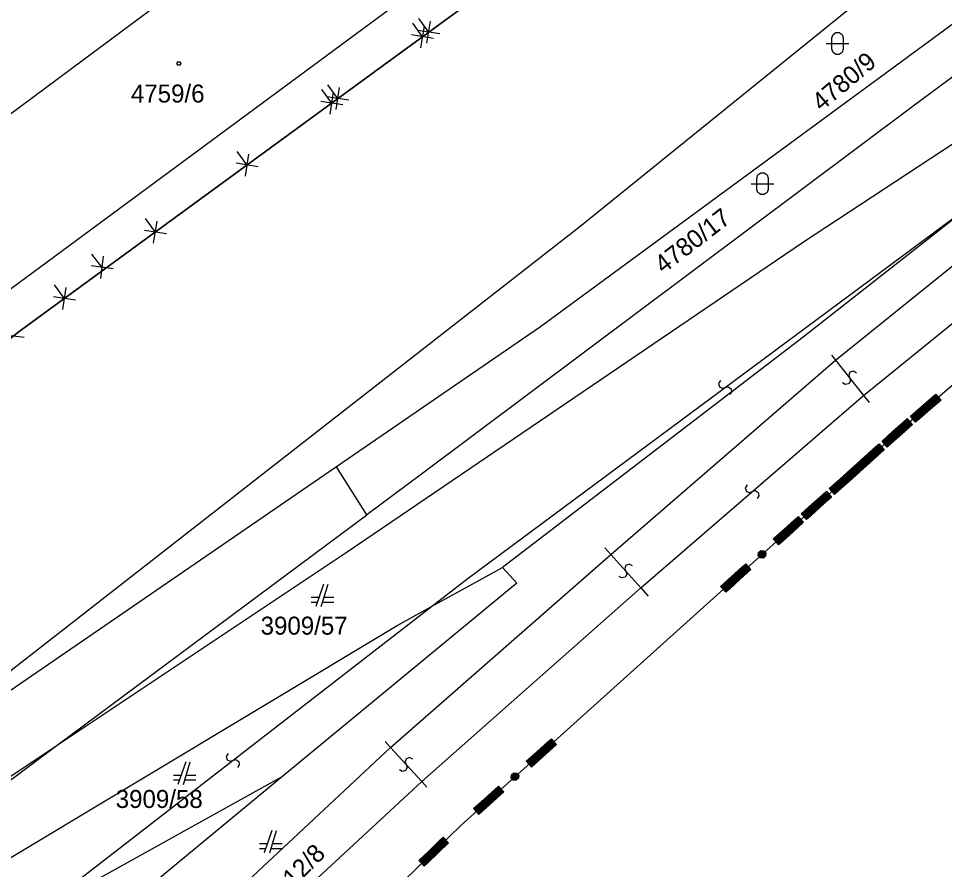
# Model space of a CAD drawing. Extents: x -266179 to -264727, y -1243225 to -1241702.
# Drawn here: x -265525.4 to -265443.1, y -1243065.9 to -1242990.2 of the extents above; entities that cross this region are included whole.
import ezdxf

# ---------------------------------------------------------------- set-up
doc = ezdxf.new("R2010")
doc.units = 0
for name, color, linetype in [('Vrstva 1', 7, 'Continuous'), ('Vrstva 19', 7, 'Continuous'), ('Vrstva 2', 7, 'Continuous'), ('Vrstva 21', 7, 'Continuous')]:
    doc.layers.add(name, color=color, linetype=linetype)

msp = doc.modelspace()

# ---------------------------------------------------------------- linework, layer by layer
at = {"layer": 'Vrstva 1'}
for p, q in [((-265475.52, -1243008.72), (-265434.39, -1242975.43)), ((-265495.14, -1242975.72), (-265534.92, -1243005.24)), ((-265418.16, -1242977.61), (-265445.92, -1242998.02)), ((-265455.74, -1243010.14), (-265412.81, -1242981.9)), ((-265527.48, -1243015.25), (-265487.69, -1242985.87)), ((-265485.47, -1242988.9), (-265493, -1242994.41)), ((-265440.4, -1242989.28), (-265479.04, -1243017.66)), ((-265493, -1242994.41), (-265525.37, -1243018.08)), ((-265445.92, -1242998.02), (-265489.73, -1243030.85)), ((-265439.81, -1243006.11), (-265455.69, -1243018.57)), ((-265534.18, -1243054.5), (-265475.52, -1243008.72)), ((-265496.21, -1243037.67), (-265455.74, -1243010.14)), ((-265431.41, -1243013.36), (-265447.33, -1243027.08)), ((-265525.37, -1243018.08), (-265529.85, -1243021.55)), ((-265479.04, -1243017.66), (-265497.17, -1243030.1)), ((-265455.69, -1243018.57), (-265482.42, -1243039.05)), ((-265447.33, -1243027.08), (-265454.5, -1243033.53)), ((-265497.17, -1243030.1), (-265541.9, -1243060.8)), ((-265494.46, -1243034.38), (-265497.17, -1243030.1)), ((-265489.73, -1243030.85), (-265494.46, -1243034.38)), ((-265454.5, -1243033.53), (-265486.12, -1243061.99)), ((-265522, -1243054.85), (-265494.46, -1243034.38)), ((-265522, -1243054.85), (-265496.21, -1243037.67)), ((-265488.71, -1243042.52), (-265482.42, -1243039.05)), ((-265482.42, -1243039.05), (-265481.14, -1243040.45)), ((-265481.14, -1243040.45), (-265501.93, -1243057.61)), ((-265498.31, -1243040.53), (-265499.01, -1243042.53)), ((-265498.51, -1243042.53), (-265497.91, -1243040.53)), ((-265498.73, -1243041.73), (-265499.41, -1243041.73)), ((-265499.41, -1243042.13), (-265498.87, -1243042.13)), ((-265498.39, -1243042.13), (-265497.41, -1243042.13)), ((-265497.41, -1243041.73), (-265498.27, -1243041.73)), ((-265491.77, -1243044.2), (-265488.71, -1243042.52)), ((-265531.47, -1243068.04), (-265491.77, -1243044.2)), ((-265534.79, -1243063.37), (-265522, -1243054.85)), ((-265533.94, -1243063.73), (-265522, -1243054.85)), ((-265510.56, -1243056.33), (-265511.26, -1243058.33)), ((-265510.76, -1243058.33), (-265510.16, -1243056.33)), ((-265524.05, -1243069.88), (-265501.93, -1243057.61)), ((-265501.93, -1243057.61), (-265523.24, -1243075.2)), ((-265510.98, -1243057.53), (-265511.66, -1243057.53)), ((-265509.66, -1243057.53), (-265510.52, -1243057.53)), ((-265511.66, -1243057.93), (-265511.12, -1243057.93)), ((-265510.64, -1243057.93), (-265509.66, -1243057.93)), ((-265502.9, -1243062.43), (-265503.6, -1243064.43)), ((-265503.1, -1243064.43), (-265502.5, -1243062.43)), ((-265486.12, -1243061.99), (-265499.6, -1243075.05)), ((-265503.32, -1243063.63), (-265504, -1243063.63)), ((-265504, -1243064.03), (-265503.46, -1243064.03)), ((-265502.98, -1243064.03), (-265502, -1243064.03)), ((-265502, -1243063.63), (-265502.86, -1243063.63))]:
    msp.add_line(p, q, dxfattribs=at)
for points in [[(-265453.13, -1242991.96), (-265453.03, -1242991.67), (-265452.78, -1242991.49), (-265452.47, -1242991.49), (-265452.22, -1242991.67), (-265452.12, -1242991.96), (-265452.12, -1242992.96), (-265452.22, -1242993.25), (-265452.47, -1242993.43), (-265452.78, -1242993.43), (-265453.03, -1242993.25), (-265453.13, -1242992.96)], [(-265511.09, -1242994.09), (-265511, -1242994.24), (-265511.09, -1242994.39), (-265511.27, -1242994.39), (-265511.36, -1242994.24), (-265511.27, -1242994.09)], [(-265459.8, -1243004.43), (-265459.7, -1243004.14), (-265459.45, -1243003.96), (-265459.14, -1243003.96), (-265458.89, -1243004.14), (-265458.79, -1243004.43), (-265458.79, -1243005.43), (-265458.89, -1243005.72), (-265459.14, -1243005.9), (-265459.45, -1243005.9), (-265459.7, -1243005.72), (-265459.8, -1243005.43)]]:
    msp.add_lwpolyline(points, close=True, dxfattribs=at)
for points in [[(-265453.63, -1242992.46), (-265452.36, -1242992.46), (-265451.63, -1242992.46)], [(-265460.3, -1243004.93), (-265459.03, -1243004.93), (-265458.3, -1243004.93)]]:
    msp.add_lwpolyline(points, dxfattribs=at)
at = {"layer": 'Vrstva 19'}
for p, q in [((-265431.41, -1243013.36), (-265447.33, -1243027.08)), ((-265447.33, -1243027.08), (-265454.5, -1243033.53)), ((-265454.5, -1243033.53), (-265486.12, -1243061.99)), ((-265486.12, -1243061.99), (-265499.6, -1243075.05))]:
    msp.add_line(p, q, dxfattribs=at)
for points in [[(-265443.427, -1243024.179), (-265444.389, -1243025.008), (-265445.351, -1243025.837), (-265445.7, -1243026.138), (-265446.157, -1243025.608), (-265445.195, -1243024.778), (-265444.233, -1243023.949), (-265443.884, -1243023.649), (-265443.427, -1243024.179), (-265443.526, -1243024.172), (-265444.488, -1243025.001), (-265445.45, -1243025.83), (-265445.708, -1243026.052), (-265445.76, -1243025.991), (-265444.798, -1243025.162), (-265443.836, -1243024.333), (-265443.578, -1243024.111), (-265443.631, -1243024.051), (-265444.593, -1243024.88), (-265445.555, -1243025.709), (-265445.812, -1243025.931), (-265445.864, -1243025.87), (-265444.902, -1243025.041), (-265443.94, -1243024.212), (-265443.683, -1243023.99), (-265443.735, -1243023.929), (-265444.697, -1243024.759), (-265445.659, -1243025.588), (-265445.917, -1243025.81), (-265445.969, -1243025.749), (-265445.007, -1243024.92), (-265444.045, -1243024.091), (-265443.787, -1243023.869), (-265443.84, -1243023.808), (-265444.802, -1243024.637), (-265445.763, -1243025.466), (-265446.021, -1243025.688), (-265446.073, -1243025.628), (-265445.111, -1243024.799), (-265444.149, -1243023.97), (-265443.892, -1243023.748)], [(-265445.976, -1243026.334), (-265446.92, -1243027.183), (-265447.865, -1243028.032), (-265448.207, -1243028.34), (-265448.675, -1243027.819), (-265447.73, -1243026.97), (-265446.786, -1243026.121), (-265446.444, -1243025.813), (-265445.976, -1243026.334), (-265446.06, -1243026.315), (-265447.004, -1243027.164), (-265447.949, -1243028.014), (-265448.201, -1243028.241), (-265448.255, -1243028.181), (-265447.311, -1243027.332), (-265446.366, -1243026.483), (-265446.113, -1243026.256), (-265446.167, -1243026.196), (-265447.111, -1243027.045), (-265448.056, -1243027.895), (-265448.308, -1243028.122), (-265448.362, -1243028.062), (-265447.418, -1243027.213), (-265446.473, -1243026.364), (-265446.22, -1243026.137), (-265446.274, -1243026.077), (-265447.218, -1243026.926), (-265448.163, -1243027.776), (-265448.415, -1243028.003), (-265448.469, -1243027.944), (-265447.525, -1243027.094), (-265446.58, -1243026.245), (-265446.327, -1243026.018), (-265446.381, -1243025.958), (-265447.325, -1243026.807), (-265448.27, -1243027.657), (-265448.522, -1243027.884), (-265448.576, -1243027.825), (-265447.632, -1243026.975), (-265446.687, -1243026.126), (-265446.434, -1243025.899)], [(-265448.471, -1243028.578), (-265449.415, -1243029.427), (-265450.359, -1243030.277), (-265450.702, -1243030.584), (-265451.17, -1243030.064), (-265450.225, -1243029.214), (-265449.281, -1243028.365), (-265448.939, -1243028.058), (-265448.471, -1243028.578), (-265448.555, -1243028.56), (-265449.499, -1243029.409), (-265450.443, -1243030.258), (-265450.696, -1243030.485), (-265450.75, -1243030.426), (-265449.805, -1243029.577), (-265448.861, -1243028.727), (-265448.608, -1243028.5), (-265448.662, -1243028.441), (-265449.606, -1243029.29), (-265450.55, -1243030.139), (-265450.803, -1243030.366), (-265450.857, -1243030.307), (-265449.912, -1243029.458), (-265448.968, -1243028.608), (-265448.715, -1243028.381), (-265448.769, -1243028.322), (-265449.713, -1243029.171), (-265450.657, -1243030.02), (-265450.91, -1243030.247), (-265450.964, -1243030.188), (-265450.019, -1243029.339), (-265449.075, -1243028.489), (-265448.822, -1243028.262), (-265448.876, -1243028.203), (-265449.82, -1243029.052), (-265450.764, -1243029.901), (-265451.017, -1243030.128), (-265451.071, -1243030.069), (-265450.126, -1243029.22), (-265449.182, -1243028.37), (-265448.929, -1243028.143)], [(-265449.357, -1243029.334), (-265449.558, -1243029.514), (-265449.826, -1243029.5), (-265450.007, -1243029.299), (-265449.992, -1243029.031), (-265449.792, -1243028.851), (-265449.523, -1243028.865), (-265449.343, -1243029.066), (-265449.357, -1243029.334), (-265449.391, -1243029.311), (-265449.57, -1243029.471), (-265449.683, -1243029.465), (-265449.385, -1243029.198), (-265449.379, -1243029.085), (-265449.796, -1243029.459), (-265449.849, -1243029.4), (-265449.433, -1243029.025), (-265449.486, -1243028.966), (-265449.903, -1243029.34), (-265449.956, -1243029.281), (-265449.54, -1243028.906), (-265449.653, -1243028.9), (-265449.95, -1243029.168), (-265449.944, -1243029.055), (-265449.766, -1243028.894)], [(-265450.66, -1243030.546), (-265451.605, -1243031.396), (-265452.549, -1243032.245), (-265452.891, -1243032.552), (-265453.359, -1243032.032), (-265452.415, -1243031.183), (-265451.471, -1243030.333), (-265451.128, -1243030.026), (-265450.66, -1243030.546), (-265450.759, -1243030.541), (-265451.704, -1243031.39), (-265452.648, -1243032.24), (-265452.901, -1243032.467), (-265452.954, -1243032.407), (-265452.01, -1243031.558), (-265451.066, -1243030.709), (-265450.813, -1243030.482), (-265450.866, -1243030.422), (-265451.811, -1243031.271), (-265452.755, -1243032.121), (-265453.008, -1243032.348), (-265453.061, -1243032.288), (-265452.117, -1243031.439), (-265451.173, -1243030.59), (-265450.92, -1243030.363), (-265450.973, -1243030.303), (-265451.918, -1243031.152), (-265452.862, -1243032.002), (-265453.115, -1243032.229), (-265453.168, -1243032.169), (-265452.224, -1243031.32), (-265451.28, -1243030.471), (-265451.027, -1243030.244), (-265451.08, -1243030.184), (-265452.025, -1243031.033), (-265452.969, -1243031.883), (-265453.222, -1243032.11), (-265453.275, -1243032.05), (-265452.331, -1243031.201), (-265451.387, -1243030.352), (-265451.134, -1243030.125)], [(-265451.852, -1243031.578), (-265452.053, -1243031.759), (-265452.321, -1243031.744), (-265452.501, -1243031.544), (-265452.487, -1243031.275), (-265452.286, -1243031.095), (-265452.018, -1243031.109), (-265451.838, -1243031.31), (-265451.852, -1243031.578), (-265451.886, -1243031.555), (-265452.064, -1243031.716), (-265452.177, -1243031.71), (-265451.88, -1243031.442), (-265451.874, -1243031.329), (-265452.29, -1243031.704), (-265452.344, -1243031.644), (-265451.927, -1243031.27), (-265451.981, -1243031.21), (-265452.397, -1243031.585), (-265452.451, -1243031.525), (-265452.034, -1243031.151), (-265452.147, -1243031.145), (-265452.445, -1243031.412), (-265452.439, -1243031.299), (-265452.26, -1243031.139)], [(-265453.155, -1243032.791), (-265454.1, -1243033.64), (-265455.044, -1243034.489), (-265455.386, -1243034.797), (-265455.854, -1243034.276), (-265454.91, -1243033.427), (-265453.965, -1243032.578), (-265453.623, -1243032.27), (-265453.155, -1243032.791), (-265453.254, -1243032.785), (-265454.198, -1243033.635), (-265455.143, -1243034.484), (-265455.396, -1243034.711), (-265455.449, -1243034.652), (-265454.505, -1243033.803), (-265453.56, -1243032.953), (-265453.308, -1243032.726), (-265453.361, -1243032.666), (-265454.305, -1243033.516), (-265455.25, -1243034.365), (-265455.503, -1243034.592), (-265455.556, -1243034.533), (-265454.612, -1243033.684), (-265453.667, -1243032.834), (-265453.415, -1243032.607), (-265453.468, -1243032.548), (-265454.412, -1243033.397), (-265455.357, -1243034.246), (-265455.61, -1243034.473), (-265455.663, -1243034.414), (-265454.719, -1243033.565), (-265453.774, -1243032.715), (-265453.522, -1243032.488), (-265453.575, -1243032.429), (-265454.519, -1243033.278), (-265455.464, -1243034.127), (-265455.717, -1243034.354), (-265455.77, -1243034.295), (-265454.826, -1243033.446), (-265453.881, -1243032.596), (-265453.629, -1243032.369)], [(-265455.64, -1243035.029), (-265456.584, -1243035.879), (-265457.528, -1243036.728), (-265457.87, -1243037.035), (-265458.338, -1243036.515), (-265457.394, -1243035.666), (-265456.45, -1243034.816), (-265456.108, -1243034.509), (-265455.64, -1243035.029), (-265455.724, -1243035.011), (-265456.668, -1243035.86), (-265457.612, -1243036.709), (-265457.865, -1243036.937), (-265457.919, -1243036.877), (-265456.974, -1243036.028), (-265456.03, -1243035.179), (-265455.777, -1243034.951), (-265455.831, -1243034.892), (-265456.775, -1243035.741), (-265457.719, -1243036.59), (-265457.972, -1243036.818), (-265458.026, -1243036.758), (-265457.081, -1243035.909), (-265456.137, -1243035.06), (-265455.884, -1243034.832), (-265455.938, -1243034.773), (-265456.882, -1243035.622), (-265457.826, -1243036.471), (-265458.079, -1243036.699), (-265458.133, -1243036.639), (-265457.188, -1243035.79), (-265456.244, -1243034.941), (-265455.991, -1243034.713), (-265456.045, -1243034.654), (-265456.989, -1243035.503), (-265457.933, -1243036.352), (-265458.186, -1243036.58), (-265458.24, -1243036.52), (-265457.295, -1243035.671), (-265456.351, -1243034.822), (-265456.098, -1243034.594)], [(-265459.021, -1243038.029), (-265459.221, -1243038.21), (-265459.49, -1243038.196), (-265459.67, -1243037.995), (-265459.656, -1243037.727), (-265459.455, -1243037.546), (-265459.187, -1243037.56), (-265459.006, -1243037.761), (-265459.021, -1243038.029), (-265459.055, -1243038.006), (-265459.233, -1243038.167), (-265459.346, -1243038.161), (-265459.049, -1243037.893), (-265459.043, -1243037.78), (-265459.459, -1243038.155), (-265459.513, -1243038.095), (-265459.096, -1243037.721), (-265459.15, -1243037.661), (-265459.566, -1243038.036), (-265459.62, -1243037.976), (-265459.203, -1243037.602), (-265459.316, -1243037.596), (-265459.614, -1243037.863), (-265459.608, -1243037.75), (-265459.429, -1243037.59)], [(-265460.324, -1243039.242), (-265461.268, -1243040.091), (-265462.213, -1243040.94), (-265462.555, -1243041.248), (-265463.023, -1243040.727), (-265462.079, -1243039.878), (-265461.134, -1243039.029), (-265460.792, -1243038.721), (-265460.324, -1243039.242), (-265460.423, -1243039.237), (-265461.367, -1243040.086), (-265462.312, -1243040.935), (-265462.564, -1243041.162), (-265462.618, -1243041.103), (-265461.674, -1243040.254), (-265460.729, -1243039.405), (-265460.476, -1243039.177), (-265460.53, -1243039.118), (-265461.474, -1243039.967), (-265462.419, -1243040.816), (-265462.671, -1243041.044), (-265462.725, -1243040.984), (-265461.781, -1243040.135), (-265460.836, -1243039.286), (-265460.583, -1243039.058), (-265460.637, -1243038.999), (-265461.581, -1243039.848), (-265462.526, -1243040.697), (-265462.778, -1243040.925), (-265462.832, -1243040.865), (-265461.888, -1243040.016), (-265460.943, -1243039.167), (-265460.69, -1243038.939), (-265460.744, -1243038.88), (-265461.688, -1243039.729), (-265462.633, -1243040.578), (-265462.885, -1243040.806), (-265462.939, -1243040.746), (-265461.995, -1243039.897), (-265461.05, -1243039.048), (-265460.797, -1243038.82)], [(-265477.597, -1243054.793), (-265478.541, -1243055.642), (-265479.486, -1243056.491), (-265479.828, -1243056.799), (-265480.296, -1243056.278), (-265479.352, -1243055.429), (-265478.407, -1243054.58), (-265478.065, -1243054.272), (-265477.597, -1243054.793), (-265477.681, -1243054.774), (-265478.625, -1243055.623), (-265479.57, -1243056.472), (-265479.823, -1243056.7), (-265479.876, -1243056.64), (-265478.932, -1243055.791), (-265477.987, -1243054.942), (-265477.735, -1243054.714), (-265477.788, -1243054.655), (-265478.732, -1243055.504), (-265479.677, -1243056.353), (-265479.93, -1243056.581), (-265479.983, -1243056.521), (-265479.039, -1243055.672), (-265478.094, -1243054.823), (-265477.842, -1243054.595), (-265477.895, -1243054.536), (-265478.839, -1243055.385), (-265479.784, -1243056.234), (-265480.037, -1243056.462), (-265480.09, -1243056.402), (-265479.146, -1243055.553), (-265478.201, -1243054.704), (-265477.949, -1243054.476), (-265478.002, -1243054.417), (-265478.946, -1243055.266), (-265479.891, -1243056.115), (-265480.144, -1243056.343), (-265480.197, -1243056.283), (-265479.253, -1243055.434), (-265478.308, -1243054.585), (-265478.056, -1243054.358)], [(-265480.978, -1243057.793), (-265481.179, -1243057.973), (-265481.447, -1243057.959), (-265481.628, -1243057.758), (-265481.613, -1243057.49), (-265481.413, -1243057.309), (-265481.144, -1243057.323), (-265480.964, -1243057.524), (-265480.978, -1243057.793), (-265481.012, -1243057.77), (-265481.191, -1243057.93), (-265481.304, -1243057.924), (-265481.006, -1243057.657), (-265481, -1243057.544), (-265481.417, -1243057.918), (-265481.47, -1243057.859), (-265481.054, -1243057.484), (-265481.107, -1243057.425), (-265481.524, -1243057.799), (-265481.577, -1243057.74), (-265481.161, -1243057.365), (-265481.274, -1243057.359), (-265481.571, -1243057.627), (-265481.565, -1243057.514), (-265481.387, -1243057.353)], [(-265482.282, -1243059.005), (-265483.226, -1243059.854), (-265484.17, -1243060.704), (-265484.512, -1243061.011), (-265484.98, -1243060.491), (-265484.036, -1243059.641), (-265483.092, -1243058.792), (-265482.75, -1243058.485), (-265482.282, -1243059.005), (-265482.38, -1243059), (-265483.325, -1243059.849), (-265484.269, -1243060.698), (-265484.522, -1243060.926), (-265484.575, -1243060.866), (-265483.631, -1243060.017), (-265482.687, -1243059.168), (-265482.434, -1243058.94), (-265482.487, -1243058.881), (-265483.432, -1243059.73), (-265484.376, -1243060.579), (-265484.629, -1243060.807), (-265484.682, -1243060.747), (-265483.738, -1243059.898), (-265482.794, -1243059.049), (-265482.541, -1243058.821), (-265482.594, -1243058.762), (-265483.539, -1243059.611), (-265484.483, -1243060.46), (-265484.736, -1243060.688), (-265484.789, -1243060.628), (-265483.845, -1243059.779), (-265482.901, -1243058.93), (-265482.648, -1243058.702), (-265482.701, -1243058.643), (-265483.646, -1243059.492), (-265484.59, -1243060.341), (-265484.843, -1243060.569), (-265484.896, -1243060.509), (-265483.952, -1243059.66), (-265483.008, -1243058.811), (-265482.755, -1243058.583)], [(-265487.205, -1243063.529), (-265488.117, -1243064.413), (-265489.029, -1243065.296), (-265489.36, -1243065.616), (-265489.847, -1243065.114), (-265488.934, -1243064.23), (-265488.022, -1243063.346), (-265487.692, -1243063.026), (-265487.205, -1243063.529), (-265487.289, -1243063.514), (-265488.202, -1243064.397), (-265489.114, -1243065.281), (-265489.358, -1243065.517), (-265489.414, -1243065.46), (-265488.501, -1243064.576), (-265487.589, -1243063.693), (-265487.345, -1243063.456), (-265487.401, -1243063.399), (-265488.313, -1243064.282), (-265489.225, -1243065.166), (-265489.469, -1243065.402), (-265489.525, -1243065.345), (-265488.613, -1243064.461), (-265487.7, -1243063.578), (-265487.456, -1243063.341), (-265487.512, -1243063.284), (-265488.424, -1243064.167), (-265489.336, -1243065.051), (-265489.581, -1243065.288), (-265489.636, -1243065.23), (-265488.724, -1243064.347), (-265487.812, -1243063.463), (-265487.568, -1243063.226), (-265487.623, -1243063.169), (-265488.535, -1243064.053), (-265489.448, -1243064.936), (-265489.692, -1243065.173), (-265489.748, -1243065.115), (-265488.835, -1243064.232), (-265487.923, -1243063.348), (-265487.679, -1243063.111)]]:
    msp.add_lwpolyline(points, dxfattribs=at)
at = {"layer": 'Vrstva 2'}
for p, q in [((-265452.8, -1243020.63), (-265434.31, -1243005.69)), ((-265485.45, -1243039.99), (-265439.81, -1243006.11)), ((-265450.32, -1243023.75), (-265431.82, -1243008.76)), ((-265472.78, -1243037.88), (-265452.8, -1243020.63)), ((-265453.17, -1243020.17), (-265452.8, -1243020.63)), ((-265452.8, -1243020.63), (-265450.32, -1243023.75)), ((-265470.12, -1243040.87), (-265450.32, -1243023.75)), ((-265450.32, -1243023.75), (-265449.83, -1243024.37)), ((-265492.37, -1243055.04), (-265472.78, -1243037.88)), ((-265473.3, -1243037.29), (-265472.78, -1243037.88)), ((-265472.78, -1243037.88), (-265470.12, -1243040.87)), ((-265488.71, -1243042.52), (-265485.45, -1243039.99)), ((-265489.57, -1243058.08), (-265470.12, -1243040.87)), ((-265470.12, -1243040.87), (-265469.47, -1243041.6)), ((-265524.05, -1243069.88), (-265488.71, -1243042.52)), ((-265509.83, -1243071.37), (-265492.37, -1243055.04)), ((-265492.84, -1243054.52), (-265492.37, -1243055.04)), ((-265492.37, -1243055.04), (-265489.57, -1243058.08)), ((-265507.1, -1243074.3), (-265489.57, -1243058.08)), ((-265489.57, -1243058.08), (-265489.12, -1243058.57))]:
    msp.add_line(p, q, dxfattribs=at)
for points in [[(-265450.942, -1243021.762), (-265451.221, -1243021.588), (-265451.524, -1243021.689), (-265451.633, -1243021.954), (-265451.478, -1243022.47), (-265451.651, -1243022.735), (-265451.962, -1243022.778), (-265452.178, -1243022.618)], [(-265463.037, -1243022.418), (-265463.22, -1243022.691), (-265463.13, -1243022.998), (-265462.868, -1243023.115), (-265462.348, -1243022.977), (-265462.088, -1243023.158), (-265462.056, -1243023.471), (-265462.223, -1243023.682)], [(-265460.673, -1243031.71), (-265460.835, -1243031.996), (-265460.722, -1243032.295), (-265460.453, -1243032.392), (-265459.944, -1243032.217), (-265459.672, -1243032.378), (-265459.616, -1243032.687), (-265459.767, -1243032.91)], [(-265470.856, -1243038.914), (-265471.144, -1243038.755), (-265471.442, -1243038.873), (-265471.536, -1243039.143), (-265471.353, -1243039.65), (-265471.511, -1243039.924), (-265471.819, -1243039.984), (-265472.044, -1243039.836)], [(-265506.8, -1243055.576), (-265506.977, -1243055.853), (-265506.881, -1243056.158), (-265506.617, -1243056.27), (-265506.099, -1243056.122), (-265505.836, -1243056.298), (-265505.798, -1243056.609), (-265505.96, -1243056.824)], [(-265490.385, -1243056.089), (-265490.676, -1243055.935), (-265490.971, -1243056.058), (-265491.06, -1243056.33), (-265490.868, -1243056.833), (-265491.021, -1243057.11), (-265491.328, -1243057.175), (-265491.555, -1243057.031)]]:
    msp.add_lwpolyline(points, dxfattribs=at)
at = {"layer": 'Vrstva 21'}
for p, q in [((-265485.47, -1242988.9), (-265493, -1242994.41)), ((-265493, -1242994.41), (-265485.47, -1242988.9)), ((-265488.966, -1242991.456), (-265489.851, -1242990.245)), ((-265489.504, -1242991.854), (-265490.39, -1242990.643)), ((-265489.656, -1242992.832), (-265489.352, -1242990.876)), ((-265489.118, -1242992.434), (-265488.814, -1242990.478)), ((-265488.526, -1242992.006), (-265490.482, -1242991.702)), ((-265487.988, -1242991.608), (-265489.944, -1242991.304)), ((-265493, -1242994.41), (-265525.37, -1243018.08)), ((-265525.37, -1243018.08), (-265493, -1242994.41)), ((-265497.576, -1242997.757), (-265498.462, -1242996.546)), ((-265497.036, -1242997.361), (-265497.922, -1242996.15)), ((-265497.728, -1242998.735), (-265497.424, -1242996.778)), ((-265497.188, -1242998.339), (-265496.884, -1242996.383)), ((-265496.598, -1242997.909), (-265498.554, -1242997.605)), ((-265496.058, -1242997.513), (-265498.014, -1242997.209)), ((-265505.108, -1243003.264), (-265505.994, -1243002.053)), ((-265505.26, -1243004.242), (-265504.956, -1243002.286)), ((-265504.13, -1243003.416), (-265506.086, -1243003.112)), ((-265513.262, -1243009.226), (-265514.147, -1243008.015)), ((-265513.414, -1243010.204), (-265513.11, -1243008.248)), ((-265512.284, -1243009.378), (-265514.24, -1243009.074)), ((-265517.992, -1243012.363), (-265518.911, -1243011.178)), ((-265518.117, -1243013.345), (-265517.868, -1243011.381)), ((-265517.01, -1243012.488), (-265518.974, -1243012.239)), ((-265521.334, -1243015.129), (-265522.219, -1243013.918)), ((-265521.486, -1243016.107), (-265521.182, -1243014.151)), ((-265431.41, -1243013.36), (-265447.33, -1243027.08)), ((-265520.356, -1243015.281), (-265522.312, -1243014.977)), ((-265525.37, -1243018.08), (-265529.85, -1243021.55)), ((-265529.85, -1243021.55), (-265525.37, -1243018.08)), ((-265524.914, -1243018.614), (-265526.878, -1243018.365)), ((-265447.33, -1243027.08), (-265454.5, -1243033.53)), ((-265454.5, -1243033.53), (-265486.12, -1243061.99)), ((-265486.12, -1243061.99), (-265499.6, -1243075.05))]:
    msp.add_line(p, q, dxfattribs=at)

# ---------------------------------------------------------------- texts
at = {"layer": 'Vrstva 1'}
for s, rotation, p in [('4780/9', 40.27893, (-265454.051, -1242998.549)), ('4780/17', 37.52874, (-265468.112, -1243012.978)), ('3912/8', 44.97719, (-265502.672, -1243069.243))]:
    msp.add_text(s, height=1.6, rotation=rotation, dxfattribs=at).set_placement(p)
for s, p in [('4759/6', (-265515.433, -1242997.71)), ('3909/57', (-265503.903, -1243045.02)), ('3909/58', (-265516.783, -1243060.43))]:
    msp.add_text(s, height=1.6, dxfattribs=at).set_placement(p)

doc.saveas('drawing.dxf')
